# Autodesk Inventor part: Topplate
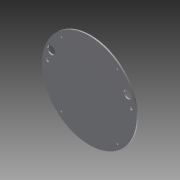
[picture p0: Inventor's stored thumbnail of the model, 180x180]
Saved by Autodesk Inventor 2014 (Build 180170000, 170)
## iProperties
Created: 2015-06
Part Number: Topplate
Material: Generic
Document SubType Name: Modeling
Designer: common
Density: 1 g/cm^3
Appearance: Default
Author: common
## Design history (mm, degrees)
node "Topplate.ipt1"
body "Solid2"
node "Base1"
